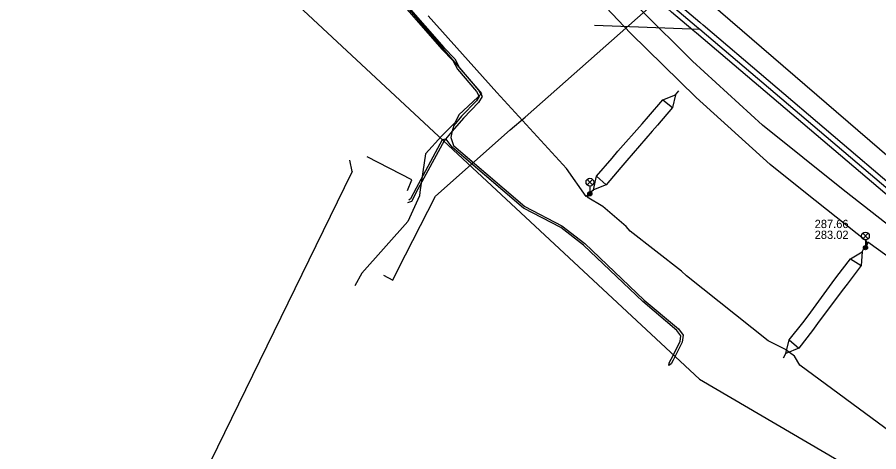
# Model space of a CAD drawing. Extents: x -595540 to -593988, y -1160850 to -1159202.
# Drawn here: x -594663.9 to -594580.6, y -1160412.6 to -1160370.6 of the extents above; entities that cross this region are included whole.
import ezdxf

# ---------------------------------------------------------------- set-up
doc = ezdxf.new("R2010")
doc.units = 0
for name, color, linetype in [('BVK-DESTOVA_popisy', 7, 'Continuous'), ('BVK-DESTOVA_trasa sítě', 7, 'Continuous'), ('BVK-DESTOVA_trasa sítě obvodem', 7, 'Continuous'), ('BVK-SPLASKOVA_trasa sítě', 7, 'Continuous'), ('CETIN_kabel podzemní', 7, 'Continuous'), ('DESTOVA_trasa neprovozované sítě', 7, 'Continuous'), ('DPMB_trolejové vedení-nosné lano', 7, 'Continuous'), ('DSP-SPLASKOVA_trasa sítě', 7, 'Continuous'), ('EON-NN_kabel', 7, 'Continuous'), ('EON-NN_kabel nadzemní', 7, 'Continuous'), ('TSB_kabel VO', 7, 'Continuous'), ('TSB_lampy VO', 7, 'Continuous')]:
    doc.layers.add(name, color=color, linetype=linetype)

msp = doc.modelspace()

# ---------------------------------------------------------------- linework, layer by layer
at = {"layer": 'BVK-DESTOVA_popisy'}
msp.add_line((-594586.818, -1160391.066), (-594586.818, -1160391.066), dxfattribs=at)
at = {"layer": 'BVK-DESTOVA_trasa sítě'}
msp.add_lwpolyline([(-594608.872, -1160362.441), (-594600.737, -1160369.346), (-594600.342, -1160369.681), (-594598.259, -1160371.449), (-594598.229, -1160371.475), (-594597.925, -1160371.733), (-594579.063, -1160387.742)], dxfattribs=at)
at = {"layer": 'BVK-DESTOVA_trasa sítě obvodem'}
for points in [[(-594578.739, -1160387.361), (-594597.601, -1160371.351), (-594597.905, -1160371.093), (-594597.935, -1160371.068), (-594600.018, -1160369.3), (-594600.414, -1160368.964), (-594608.548, -1160362.06)], [(-594579.387, -1160388.123), (-594598.248, -1160372.114), (-594598.552, -1160371.856), (-594598.583, -1160371.83), (-594600.665, -1160370.063), (-594601.061, -1160369.727), (-594609.196, -1160362.822)]]:
    msp.add_lwpolyline(points, dxfattribs=at)
at = {"layer": 'BVK-SPLASKOVA_trasa sítě'}
msp.add_lwpolyline([(-594607.618, -1160359.936), (-594600.103, -1160366.412), (-594578.449, -1160385.073)], dxfattribs=at)
at = {"layer": 'CETIN_kabel podzemní'}
for points in [[(-594677.72, -1160298.48), (-594662, -1160340.25), (-594667.08, -1160350.92), (-594656.1, -1160363.32), (-594647.95, -1160359.01), (-594597.96, -1160405.53), (-594580.17, -1160415.96), (-594522.1, -1160442.61), (-594503.24, -1160449.32), (-594487.31, -1160454.78), (-594463.83, -1160460.23), (-594443.09, -1160462.96), (-594437.19, -1160463.65)], [(-594646.8, -1160342.18), (-594642.09, -1160349.85), (-594636.15, -1160357.89), (-594627.23, -1160368.42), (-594624.8, -1160371.24), (-594619.02, -1160377.95)], [(-594619.02, -1160377.95), (-594619.4, -1160378.3), (-594621.23, -1160380.01), (-594621.58, -1160380.74), (-594622.86, -1160382.04), (-594624.43, -1160383.76), (-594625, -1160387.46), (-594625.03, -1160387.83), (-594626.16, -1160390.29), (-594630.59, -1160395.29), (-594631.29, -1160396.53)]]:
    msp.add_lwpolyline(points, dxfattribs=at)
at = {"layer": 'DESTOVA_trasa neprovozované sítě'}
msp.add_line((-594608.106, -1160371.336), (-594597.925, -1160371.733), dxfattribs=at)
at = {"layer": 'DPMB_trolejové vedení-nosné lano'}
for points in [[(-594608.621, -1160387.524), (-594608.211, -1160387.247), (-594607.905, -1160385.938), (-594606.406, -1160384.202), (-594605.838, -1160383.495), (-594603.495, -1160380.857), (-594602.885, -1160380.166), (-594601.488, -1160378.547), (-594600.269, -1160378.052), (-594599.938, -1160377.689)], [(-594600.269, -1160378.052), (-594600.552, -1160379.297), (-594602.017, -1160380.986), (-594602.523, -1160381.567), (-594604.977, -1160384.416), (-594605.564, -1160385.073), (-594606.977, -1160386.764), (-594608.211, -1160387.247)], [(-594601.488, -1160378.547), (-594600.552, -1160379.297)], [(-594607.905, -1160385.938), (-594606.977, -1160386.764)], [(-594589.836, -1160403.474), (-594589.6, -1160403.073), (-594589.277, -1160401.734), (-594587.979, -1160400.093), (-594587.463, -1160399.417), (-594585.142, -1160396.223), (-594584.671, -1160395.614), (-594583.342, -1160393.927), (-594582.225, -1160393.249), (-594582.039, -1160392.841)], [(-594582.225, -1160393.249), (-594582.31, -1160394.557), (-594583.669, -1160396.351), (-594584.17, -1160396.981), (-594586.548, -1160400.167), (-594587.03, -1160400.845), (-594588.349, -1160402.553), (-594589.6, -1160403.073)], [(-594583.342, -1160393.927), (-594582.31, -1160394.557)], [(-594589.277, -1160401.734), (-594588.349, -1160402.553)]]:
    msp.add_lwpolyline(points, dxfattribs=at)
at = {"layer": 'DSP-SPLASKOVA_trasa sítě'}
for p, q in [((-594614.794, -1160380.212), (-594600.867, -1160367.885)), ((-594616.255, -1160381.458), (-594614.794, -1160380.212)), ((-594623.464, -1160387.858), (-594616.255, -1160381.458)), ((-594627.113, -1160394.98), (-594623.464, -1160387.858)), ((-594628.505, -1160395.503), (-594627.615, -1160395.959)), ((-594627.615, -1160395.959), (-594627.113, -1160394.98))]:
    msp.add_line(p, q, dxfattribs=at)
at = {"layer": 'EON-NN_kabel'}
for points in [[(-594620.088, -1160346.405), (-594620.501, -1160345.978), (-594623.054, -1160347.754), (-594625.603, -1160349.528), (-594634.367, -1160356.855), (-594635.869, -1160357.887), (-594635.993, -1160358.453), (-594635.486, -1160359.2), (-594622.865, -1160373.648), (-594621.813, -1160374.738), (-594621.362, -1160375.584), (-594619.525, -1160377.749), (-594619.245, -1160378.218), (-594619.519, -1160378.64), (-594620.95, -1160380.139), (-594621.711, -1160381.034), (-594621.856, -1160381.58), (-594621.89, -1160381.71)], [(-594620.299, -1160346.546), (-594620.533, -1160346.304), (-594622.823, -1160347.898), (-594625.451, -1160349.726), (-594634.215, -1160357.055), (-594635.645, -1160358.037), (-594635.725, -1160358.401), (-594635.288, -1160359.048), (-594622.681, -1160373.478), (-594621.609, -1160374.59), (-594621.154, -1160375.442), (-594619.321, -1160377.603), (-594618.951, -1160378.224), (-594619.321, -1160378.796), (-594620.764, -1160380.307), (-594621.856, -1160381.58), (-594622.524, -1160382.359), (-594622.642, -1160382.497), (-594625.172, -1160387.178), (-594625.791, -1160388.363), (-594626.197, -1160388.487)], [(-594578.002, -1160391.983), (-594584.064, -1160387.234), (-594591.879, -1160380.99), (-594598.619, -1160374.826), (-594603.62, -1160369.849), (-594609.823, -1160363.406), (-594615.108, -1160357.408), (-594621.262, -1160350.418), (-594622.139, -1160349.269), (-594622.28, -1160348.979), (-594622.259, -1160348.48), (-594620.573, -1160347.307)], [(-594621.89, -1160381.71), (-594622.01, -1160382.19), (-594621.724, -1160382.965), (-594620.605, -1160383.944), (-594614.854, -1160388.857), (-594611.266, -1160390.725), (-594609.035, -1160392.434), (-594603.293, -1160397.895), (-594599.986, -1160400.691), (-594599.536, -1160401.303), (-594599.623, -1160401.96), (-594600.512, -1160403.717), (-594600.701, -1160404.053), (-594600.91, -1160404.22), (-594600.879, -1160403.954), (-594600.688, -1160403.623), (-594599.817, -1160401.9), (-594599.744, -1160401.357), (-594600.134, -1160400.829), (-594603.427, -1160398.044), (-594609.165, -1160392.586), (-594611.374, -1160390.895), (-594614.966, -1160389.023), (-594620.735, -1160384.096), (-594621.856, -1160383.115), (-594622.46, -1160382.35), (-594622.524, -1160382.359), (-594622.818, -1160382.403), (-594625.348, -1160387.082), (-594625.891, -1160388.125), (-594626.056, -1160388.232)], [(-594626.193, -1160387.305), (-594625.769, -1160386.291), (-594630.08, -1160384.073)]]:
    msp.add_lwpolyline(points, dxfattribs=at)
at = {"layer": 'EON-NN_kabel nadzemní'}
for points in [[(-594631.549, -1160385.485), (-594631.766, -1160384.382)], [(-594631.549, -1160385.485), (-594632.311, -1160387.045), (-594647.97, -1160419.1), (-594662.31, -1160457.93)]]:
    msp.add_lwpolyline(points, dxfattribs=at)
at = {"layer": 'TSB_kabel VO'}
for points in [[(-594572.71, -1160398.73), (-594581.689, -1160392.317), (-594581.807, -1160392.698), (-594581.911, -1160392.832), (-594581.921, -1160392.663), (-594581.79, -1160392.24), (-594587.693, -1160387.532), (-594591.12, -1160384.8), (-594598.29, -1160378.33), (-594604.62, -1160372.11), (-594610.57, -1160365.83)], [(-594579.44, -1160410.68), (-594588.24, -1160404.19), (-594588.77, -1160403.32), (-594589.61, -1160402.72), (-594589.65, -1160402.67), (-594591.32, -1160401.83), (-594599.2, -1160395.56), (-594599.69, -1160395.1), (-594604.66, -1160391.23), (-594605.04, -1160390.78), (-594607.31, -1160388.86), (-594608.807, -1160387.962), (-594608.609, -1160387.77), (-594608.55, -1160387.628), (-594608.693, -1160387.684), (-594608.895, -1160387.88), (-594610.81, -1160385.18), (-594617.54, -1160377.84), (-594624.19, -1160370.42)]]:
    msp.add_lwpolyline(points, dxfattribs=at)
at = {"layer": 'TSB_lampy VO'}
for p, q in [((-594608.815, -1160386.768), (-594608.285, -1160386.238)), ((-594608.815, -1160386.238), (-594608.285, -1160386.768)), ((-594608.815, -1160386.768), (-594608.285, -1160386.238)), ((-594608.815, -1160386.238), (-594608.285, -1160386.768)), ((-594608.55, -1160386.878), (-594608.55, -1160387.628)), ((-594608.55, -1160386.878), (-594608.55, -1160387.628)), ((-594582.176, -1160391.972), (-594581.646, -1160391.442)), ((-594582.176, -1160391.442), (-594581.646, -1160391.972)), ((-594582.176, -1160391.972), (-594581.646, -1160391.442)), ((-594582.176, -1160391.442), (-594581.646, -1160391.972)), ((-594581.911, -1160392.082), (-594581.911, -1160392.832)), ((-594581.911, -1160392.082), (-594581.911, -1160392.832))]:
    msp.add_line(p, q, dxfattribs=at)
for centre, radius in [((-594608.55, -1160386.503), 0.375), ((-594608.55, -1160386.503), 0.375), ((-594608.55, -1160387.628), 0.2), ((-594608.55, -1160387.628), 0.2), ((-594608.55, -1160387.628), 0.145), ((-594608.55, -1160387.628), 0.145), ((-594608.55, -1160387.628), 0.0876), ((-594608.55, -1160387.628), 0.0876), ((-594581.911, -1160391.707), 0.375), ((-594581.911, -1160391.707), 0.375), ((-594581.911, -1160392.832), 0.2), ((-594581.911, -1160392.832), 0.2), ((-594581.911, -1160392.832), 0.145), ((-594581.911, -1160392.832), 0.145), ((-594581.911, -1160392.832), 0.0876), ((-594581.911, -1160392.832), 0.0876)]:
    msp.add_circle(centre, radius, dxfattribs=at)

# ---------------------------------------------------------------- texts
at = {"layer": 'BVK-DESTOVA_popisy'}
for s, p in [('287.66', (-594586.818, -1160390.941)), ('283.02', (-594586.818, -1160391.991))]:
    msp.add_text(s, height=0.8, dxfattribs=at).set_placement(p)

doc.saveas('drawing.dxf')
